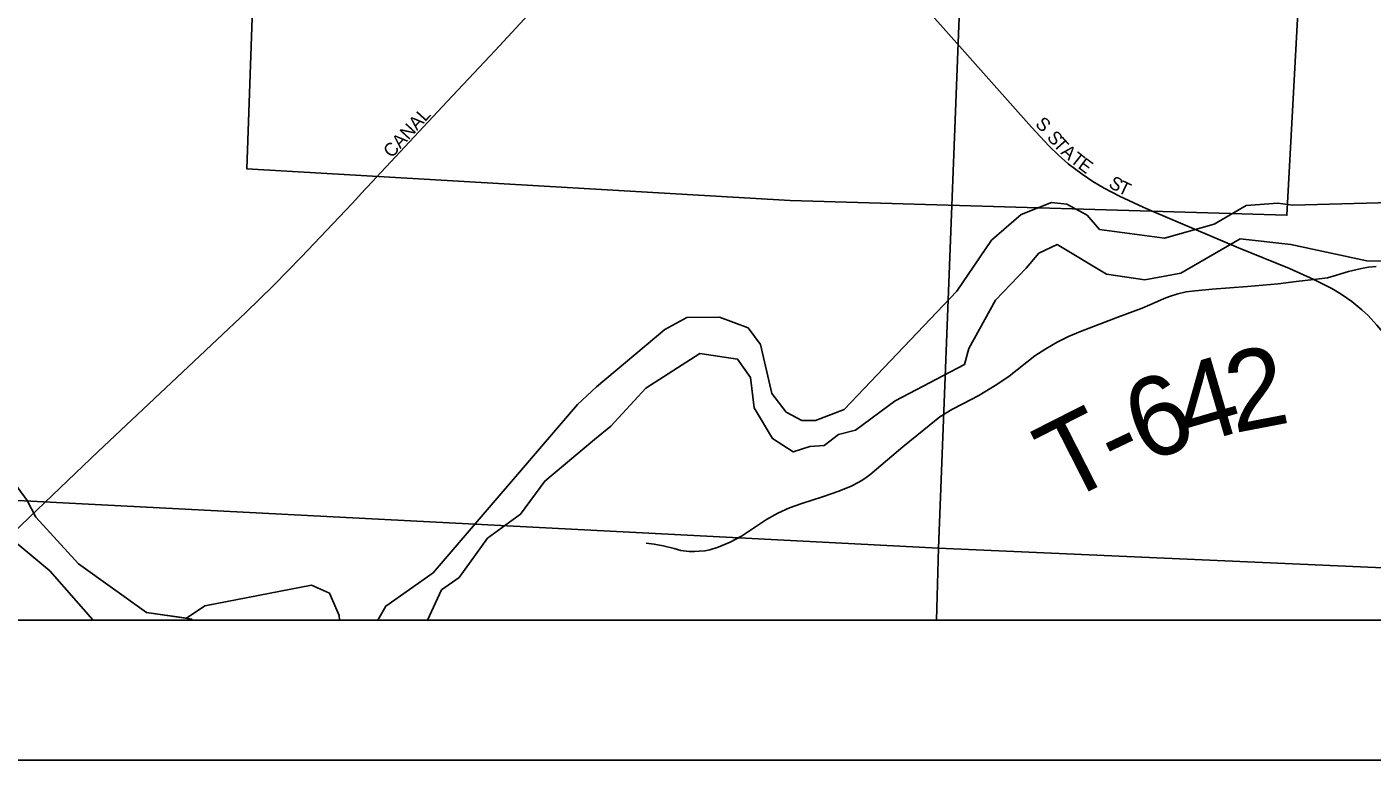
# Model space of a CAD drawing. Extents: x 0 to 34, y 0 to 22.
# Drawn here: x 24.458 to 25.417, y 14 to 14.523 of the extents above; entities that cross this region are included whole.
import ezdxf

# ---------------------------------------------------------------- set-up
doc = ezdxf.new("R2010")
doc.units = 0
for name, color, linetype in [('GM_X_Adjacent_County', 7, 'Continuous'), ('GM_X_City_Street', 7, 'Continuous'), ('GM_X_City_Street_Text', 7, 'Continuous'), ('GM_X_Corporation', 7, 'Continuous'), ('GM_X_County', 7, 'Continuous'), ('GM_X_County_Road', 7, 'Continuous'), ('GM_X_Minor_River', 7, 'Continuous'), ('GM_X_Section', 7, 'Continuous'), ('GM_X_Township', 7, 'Continuous'), ('GM_X_Township_Road', 7, 'Continuous'), ('GM_X_Township_Road_Text', 7, 'Continuous'), ('SH_Data', 7, 'Continuous')]:
    doc.layers.add(name, color=color, linetype=linetype)

msp = doc.modelspace()

# ---------------------------------------------------------------- linework, layer by layer
at = {"layer": 'GM_X_Adjacent_County'}
msp.add_lwpolyline([(24.01667, 18.0693), (24.01667, 14.1), (30.81667, 14.1), (30.81667, 17.81737)], dxfattribs=at)
at = {"layer": 'GM_X_City_Street'}
for points in [[(25.25611, 14.3938), (25.25387, 14.39477), (25.237, 14.40268), (25.22601, 14.4084), (25.21804, 14.41315), (25.21036, 14.41833), (25.20049, 14.4258), (25.19348, 14.43182), (25.18691, 14.43829), (25.17428, 14.45194), (25.1496, 14.47982), (25.1248, 14.50756), (25.08987, 14.54713), (25.0777, 14.56131), (25.04968, 14.59351), (25.02732, 14.61907), (25.00329, 14.64741), (25.00148, 14.64984), (24.99984, 14.65236), (24.99833, 14.65491), (24.99756, 14.65639)], [(24.69894, 14.40751), (24.70034, 14.40903), (24.75754, 14.47027), (24.79182, 14.50653), (24.81835, 14.53533)]]:
    msp.add_lwpolyline(points, dxfattribs=at)
at = {"layer": 'GM_X_Corporation'}
msp.add_lwpolyline([(25.62787, 15.25304), (25.39901, 15.0362), (25.38711, 15.02549), (25.39055, 15.01962), (25.35642, 14.38899), (25.00223, 14.39963), (24.6145, 14.42219), (24.62302, 14.65816), (24.28934, 14.51924), (24.31045, 14.95945), (24.31458, 15.18617), (24.61779, 15.17724), (24.72674, 15.17362), (24.73507, 15.37828)], dxfattribs=at)
at = {"layer": 'GM_X_County'}
msp.add_lwpolyline([(24.01667, 18.0693), (24.01667, 14.1), (30.81667, 14.1), (30.81667, 17.81737)], dxfattribs=at)
at = {"layer": 'GM_X_County_Road'}
for points in [[(24.38207, 14.1), (24.43586, 14.1508), (24.46512, 14.17859), (24.50864, 14.22028), (24.56869, 14.27701), (24.61388, 14.31962), (24.63389, 14.3391), (24.65337, 14.35912), (24.68963, 14.39749), (24.69894, 14.40751)], [(25.3757, 14.34302), (25.35815, 14.351), (25.32189, 14.36574), (25.25979, 14.39222), (25.25611, 14.3938)], [(25.3757, 14.34302), (25.38544, 14.34439), (25.39169, 14.34622), (25.40037, 14.34881), (25.4096, 14.35093), (25.4147, 14.35198), (25.42007, 14.35251)], [(25.50933, 14.1), (25.50722, 14.10911), (25.4977, 14.14517), (25.49166, 14.16604), (25.48783, 14.1769), (25.48386, 14.18952), (25.48019, 14.20082), (25.47476, 14.2174), (25.47124, 14.22693), (25.46596, 14.24132), (25.46288, 14.24865), (25.45862, 14.2576), (25.45378, 14.26567), (25.44483, 14.27815), (25.43544, 14.29106), (25.42642, 14.30351), (25.42056, 14.31063), (25.41427, 14.31734), (25.4098, 14.32153), (25.40265, 14.32734), (25.39507, 14.33262), (25.38835, 14.33674), (25.3757, 14.34302)]]:
    msp.add_lwpolyline(points, dxfattribs=at)
at = {"layer": 'GM_X_Minor_River'}
for points in [[(25.43945, 14.39837), (25.36062, 14.39613), (25.35, 14.39761), (25.32726, 14.39599), (25.30458, 14.38261), (25.269, 14.37259), (25.22273, 14.37885), (25.21396, 14.38905), (25.19952, 14.39695), (25.18853, 14.39805), (25.16696, 14.38961), (25.14582, 14.37131), (25.12097, 14.33478), (25.04063, 14.25021), (25.02019, 14.24253), (25.01034, 14.24249), (24.99932, 14.24851), (24.98902, 14.26175), (24.9809, 14.29661), (24.97213, 14.30871), (24.95162, 14.31621), (24.92851, 14.31611), (24.91263, 14.30732), (24.86392, 14.26652), (24.85033, 14.25394), (24.74741, 14.13361), (24.71379, 14.10994), (24.70799, 14.1)], [(24.74344, 14.1), (24.75353, 14.1215), (24.766, 14.13028), (24.78634, 14.15844), (24.80976, 14.17561), (24.82708, 14.19921), (24.86258, 14.22895), (24.87428, 14.23849), (24.89917, 14.26553), (24.93772, 14.29036), (24.96465, 14.2863), (24.97381, 14.27306), (24.97656, 14.25145), (24.98955, 14.2295), (25.00438, 14.22008), (25.01611, 14.22393), (25.02634, 14.22473), (25.03654, 14.23236), (25.04865, 14.23545), (25.07698, 14.25644), (25.12652, 14.28245), (25.1295, 14.29384), (25.14867, 14.32845), (25.17055, 14.35131), (25.17959, 14.36197), (25.19246, 14.36809), (25.2278, 14.347), (25.25511, 14.34294), (25.28087, 14.34761), (25.3232, 14.37207), (25.35923, 14.36805), (25.41349, 14.35653), (25.43964, 14.35588)], [(24.57167, 14.10124), (24.5431, 14.10547), (24.49448, 14.14022), (24.46406, 14.1735), (24.45796, 14.18524), (24.44311, 14.20568)], [(24.44311, 14.20568), (24.45796, 14.18524), (24.46406, 14.1735), (24.49448, 14.14022), (24.5431, 14.10547), (24.5757, 14.10064)], [(24.45124, 14.15412), (24.47404, 14.13523), (24.50484, 14.10004), (24.50492, 14.1)], [(24.68069, 14.1), (24.68046, 14.10335), (24.67356, 14.11925), (24.66065, 14.12489), (24.58453, 14.11014), (24.57167, 14.10124)]]:
    msp.add_lwpolyline(points, dxfattribs=at)
at = {"layer": 'GM_X_Section'}
for p, q in [((24.097, 14.1), (25.10648, 14.1)), ((25.10648, 14.1), (26.12338, 14.1))]:
    msp.add_line(p, q, dxfattribs=at)
for points in [[(24.14401, 15.19968), (25.14694, 15.15424), (25.10789, 14.15143), (24.10202, 14.20337)], [(25.14694, 15.15424), (26.15851, 15.10311), (26.15237, 14.93685), (26.13408, 14.43121), (26.12359, 14.10638), (25.10789, 14.15143)]]:
    msp.add_lwpolyline(points, close=True, dxfattribs=at)
for points in [[(25.10648, 14.1), (25.10789, 14.15143), (24.10202, 14.20337), (24.097, 14.1)], [(26.12338, 14.1), (26.12359, 14.10638), (25.10789, 14.15143), (25.10648, 14.1)]]:
    msp.add_lwpolyline(points, dxfattribs=at)
at = {"layer": 'GM_X_Township'}
msp.add_lwpolyline([(24.01667, 18.0693), (24.01667, 14.1), (26.12437, 14.1)], dxfattribs=at)
at = {"layer": 'GM_X_Township_Road'}
for points in [[(25.26898, 14.32952), (25.27269, 14.33107), (25.27854, 14.33297), (25.28453, 14.33436), (25.2909, 14.33513), (25.30315, 14.33618), (25.32821, 14.33804), (25.35012, 14.34013), (25.36306, 14.34165), (25.3757, 14.34302)], [(24.8995, 14.15484), (24.9051, 14.15413), (24.91158, 14.15291), (24.91928, 14.15098), (24.92418, 14.14958), (24.93013, 14.14888), (24.93381, 14.14888), (24.93714, 14.14906), (24.94134, 14.14941), (24.94484, 14.15011), (24.95079, 14.15203), (24.95937, 14.15571), (24.96742, 14.15991), (24.97372, 14.16411), (24.9852, 14.17181), (24.99332, 14.17622), (25.00176, 14.18001), (25.01045, 14.18326), (25.02519, 14.18804), (25.03693, 14.19212), (25.04556, 14.19569), (25.05116, 14.19842), (25.05385, 14.20003), (25.05643, 14.20181), (25.05889, 14.20373), (25.06362, 14.20776), (25.08254, 14.22377), (25.09748, 14.23588), (25.10886, 14.24498), (25.11743, 14.25041), (25.12531, 14.25444), (25.13669, 14.26021), (25.14964, 14.26826), (25.15839, 14.27421), (25.17672, 14.28858), (25.18446, 14.29367), (25.19246, 14.29834), (25.20075, 14.30247), (25.20929, 14.30606), (25.23594, 14.31622), (25.25309, 14.3227), (25.26417, 14.32751), (25.26898, 14.32952)]]:
    msp.add_lwpolyline(points, dxfattribs=at)
at = {"layer": 'SH_Data'}
for points in [[(23.91667, 21), (30.91667, 21), (30.91667, 14), (23.91667, 14)], [(24.01667, 20.9), (30.81667, 20.9), (30.81667, 14.1), (24.01667, 14.1)]]:
    msp.add_lwpolyline(points, close=True, dxfattribs=at)

# ---------------------------------------------------------------- texts
at = {"layer": 'GM_X_City_Street_Text'}
for s, rotation, p in [('CANAL', 47.56571, (24.71791, 14.42935)), ('S', 314.98179, (25.17632, 14.45358)), ('S', 310.82355, (25.18475, 14.4443)), ('T', 311.80676, (25.18923, 14.43912)), ('A', 319.05326, (25.1946, 14.43324)), ('T', 321.53106, (25.20124, 14.42749)), ('E', 323.64025, (25.20676, 14.42311)), ('S', 328.67537, (25.22856, 14.40963)), ('T', 334.45801, (25.23517, 14.40566))]:
    msp.add_text(s, height=0.00947, rotation=rotation, dxfattribs=at).set_placement(p)
at = {"layer": 'GM_X_Township_Road_Text'}
for s, rotation, p in [('4', 16.27207, (25.28643, 14.22389)), ('2', 10.90577, (25.31866, 14.23337)), ('6', 21.40328, (25.25512, 14.21155)), ('T', 26.9503, (25.19749, 14.18286)), ('-', 25.44086, (25.23502, 14.20195))]:
    msp.add_text(s, height=0.05682, rotation=rotation, dxfattribs=at).set_placement(p)

doc.saveas('drawing.dxf')
